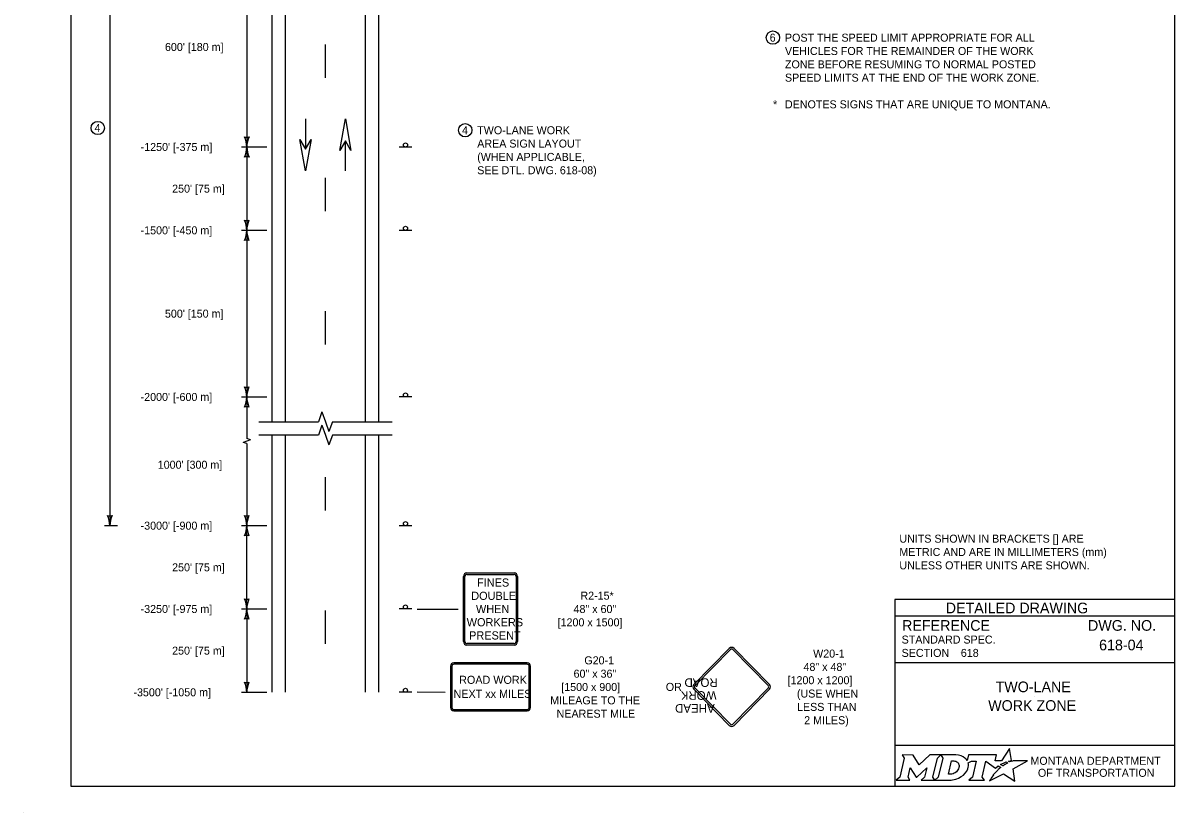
# Model space of a CAD drawing. Extents: x 49991.4 to 50021, y 49987.6 to 50011.4.
# Drawn here: x 49999.98 to 50008.61, y 49999.86 to 50005.79 of the extents above; entities that cross this region are included whole.
import ezdxf

# ---------------------------------------------------------------- set-up
doc = ezdxf.new("R2010")
doc.units = 0
for name, color, linetype in [('Level 1', 7, 'Continuous'), ('Level 2', 7, 'Continuous'), ('Level 3', 7, 'Continuous'), ('Level 6', 7, 'Continuous')]:
    doc.layers.add(name, color=color, linetype=linetype)

msp = doc.modelspace()

# ---------------------------------------------------------------- linework, layer by layer
at = {"layer": 'Level 1'}
for p, q in [((50001.8443, 50002.7972), (50001.8443, 50007.9828)), ((50001.8443, 50002.7972), (50001.8443, 50007.9828)), ((50001.9443, 50002.7972), (50001.9443, 50007.9828)), ((50001.9443, 50002.7972), (50001.9443, 50007.9828)), ((50002.5443, 50002.7972), (50002.5443, 50007.9828)), ((50002.5443, 50002.7972), (50002.5443, 50007.9828)), ((50002.6443, 50002.7972), (50002.6443, 50007.9828)), ((50002.6443, 50002.7972), (50002.6443, 50007.9828)), ((50002.2443, 50005.3756), (50002.2443, 50005.6256)), ((50002.2443, 50005.3756), (50002.2443, 50005.6256)), ((50002.0943, 50005.0679), (50002.0943, 50004.8421)), ((50002.0943, 50005.0679), (50002.0943, 50004.8421)), ((50002.0946, 50005.0679), (50002.0946, 50004.8421)), ((50002.0946, 50005.0679), (50002.0946, 50004.8421)), ((50002.394, 50004.6779), (50002.394, 50004.9037)), ((50002.394, 50004.6779), (50002.394, 50004.9037)), ((50002.8926, 50004.8574), (50002.7966, 50004.8574)), ((50002.8926, 50004.8574), (50002.7966, 50004.8574)), ((50002.2443, 50004.3756), (50002.2443, 50004.6256)), ((50002.2443, 50004.3756), (50002.2443, 50004.6256)), ((50002.8926, 50004.2323), (50002.7966, 50004.2323)), ((50002.8926, 50004.2323), (50002.7966, 50004.2323)), ((50002.2443, 50003.3756), (50002.2443, 50003.6256)), ((50002.2443, 50003.3756), (50002.2443, 50003.6256)), ((50001.9443, 50002.9828), (50001.9443, 50003.4472)), ((50001.9443, 50002.9828), (50001.9443, 50003.4472)), ((50002.5443, 50002.9828), (50002.5443, 50003.4472)), ((50002.5443, 50002.9828), (50002.5443, 50003.4472)), ((50002.8926, 50002.9824), (50002.7966, 50002.9824)), ((50002.8926, 50002.9824), (50002.7966, 50002.9824)), ((50001.8443, 50000.7675), (50001.8443, 50002.6972)), ((50001.8443, 50000.7675), (50001.8443, 50002.6972)), ((50001.9443, 50000.7675), (50001.9443, 50002.6972)), ((50001.9443, 50000.7675), (50001.9443, 50002.6972)), ((50002.5443, 50000.7675), (50002.5443, 50002.6972)), ((50002.5443, 50000.7675), (50002.5443, 50002.6972)), ((50002.6443, 50000.7675), (50002.6443, 50002.6972)), ((50002.6443, 50000.7675), (50002.6443, 50002.6972)), ((50002.2443, 50002.1309), (50002.2443, 50002.3809)), ((50002.2443, 50002.1309), (50002.2443, 50002.3809)), ((50002.8926, 50002.0171), (50002.7966, 50002.0171)), ((50002.8926, 50002.0171), (50002.7966, 50002.0171)), ((50003.2797, 50001.1475), (50003.2797, 50001.637)), ((50003.2902, 50001.1475), (50003.2902, 50001.637)), ((50003.305, 50001.6623), (50003.6594, 50001.6623)), ((50003.305, 50001.6517), (50003.6594, 50001.6517)), ((50003.4822, 50001.6623), (50003.4822, 50001.6623)), ((50003.6742, 50001.637), (50003.6742, 50001.1475)), ((50003.6847, 50001.637), (50003.6847, 50001.1475)), ((50002.2443, 50001.1309), (50002.2443, 50001.3809)), ((50002.2443, 50001.1309), (50002.2443, 50001.3809)), ((50002.8923, 50001.3923), (50002.7963, 50001.3923)), ((50002.8923, 50001.3923), (50002.7963, 50001.3923)), ((50003.6594, 50001.1327), (50003.305, 50001.1327)), ((50003.6594, 50001.1222), (50003.305, 50001.1222)), ((50005.0068, 50000.8261), (50005.272, 50001.0968)), ((50005.0157, 50000.8174), (50005.2808, 50001.0881)), ((50005.2994, 50001.0881), (50005.5646, 50000.8174)), ((50005.3083, 50001.0968), (50005.5735, 50000.8261)), ((50003.7572, 50000.988), (50003.2072, 50000.988)), ((50003.7572, 50000.988), (50003.2072, 50000.988)), ((50003.7572, 50000.978), (50003.2072, 50000.978)), ((50003.7572, 50000.978), (50003.2072, 50000.978)), ((50003.1822, 50000.963), (50003.1822, 50000.653)), ((50003.1822, 50000.963), (50003.1822, 50000.653)), ((50003.1922, 50000.963), (50003.1922, 50000.653)), ((50003.1922, 50000.963), (50003.1922, 50000.653)), ((50003.7722, 50000.653), (50003.7722, 50000.963)), ((50003.7722, 50000.653), (50003.7722, 50000.963)), ((50003.7822, 50000.653), (50003.7822, 50000.963)), ((50003.7822, 50000.653), (50003.7822, 50000.963)), ((50002.8923, 50000.7673), (50002.7963, 50000.7673)), ((50002.8923, 50000.7673), (50002.7963, 50000.7673)), ((50005.272, 50000.5192), (50005.0068, 50000.7899)), ((50005.2808, 50000.5279), (50005.0157, 50000.7986)), ((50005.5646, 50000.7986), (50005.2994, 50000.5279)), ((50005.5735, 50000.7899), (50005.3083, 50000.5192)), ((50003.2072, 50000.638), (50003.7572, 50000.638)), ((50003.2072, 50000.638), (50003.7572, 50000.638)), ((50003.2072, 50000.628), (50003.7572, 50000.628)), ((50003.2072, 50000.628), (50003.7572, 50000.628)), ((49999.9766, 49999.8624), (49999.9766, 49999.8624))]:
    msp.add_line(p, q, dxfattribs=at)
for points in [[(50008.6146, 50011.2628), (50000.3356, 50011.2628), (50000.3356, 50000.0624), (50008.6146, 50000.0624)], [(50002.3523, 50004.8315), (50002.394, 50005.0679), (50002.4359, 50004.8315), (50002.394, 50004.9037)], [(50002.3523, 50004.8315), (50002.394, 50005.0679), (50002.4359, 50004.8315), (50002.394, 50004.9037)], [(50002.1363, 50004.9143), (50002.0946, 50004.6779), (50002.0527, 50004.9143), (50002.0946, 50004.8421)], [(50002.1363, 50004.9143), (50002.0946, 50004.6779), (50002.0527, 50004.9143), (50002.0946, 50004.8421)]]:
    msp.add_lwpolyline(points, close=True, dxfattribs=at)
for centre in [(50002.8446, 50004.8726), (50002.8446, 50004.8726), (50002.8446, 50004.2476), (50002.8446, 50004.2476), (50002.8446, 50002.9976), (50002.8446, 50002.9976), (50002.8446, 50002.0323), (50002.8446, 50002.0323), (50002.8443, 50001.4075), (50002.8443, 50001.4075), (50002.8443, 50000.7825), (50002.8443, 50000.7825)]:
    msp.add_circle(centre, 0.0152, dxfattribs=at)
for centre, radius, start, end in [((50003.305, 50001.637), 0.0253, 90, 180), ((50003.305, 50001.637), 0.0148, 90, 180), ((50003.6594, 50001.637), 0.0253, 0, 90), ((50003.6594, 50001.637), 0.0148, 0, 90), ((50003.305, 50001.1475), 0.0253, 180, 270), ((50003.305, 50001.1475), 0.0148, 180, 270), ((50003.6594, 50001.1475), 0.0148, 270, 360), ((50003.6594, 50001.1475), 0.0253, 270, 360), ((50003.2072, 50000.963), 0.025, 90, 180), ((50003.2072, 50000.963), 0.025, 90, 180), ((50003.2072, 50000.963), 0.015, 90, 180), ((50003.2072, 50000.963), 0.015, 90, 180), ((50003.7572, 50000.963), 0.025, 0, 90), ((50003.7572, 50000.963), 0.025, 0, 90), ((50003.7572, 50000.963), 0.015, 0, 90), ((50003.7572, 50000.963), 0.015, 0, 90), ((50003.2072, 50000.653), 0.025, 180, 270), ((50003.2072, 50000.653), 0.025, 180, 270), ((50003.2072, 50000.653), 0.015, 180, 270), ((50003.2072, 50000.653), 0.015, 180, 270), ((50003.7572, 50000.653), 0.025, 270, 360), ((50003.7572, 50000.653), 0.015, 270, 360), ((50003.7572, 50000.653), 0.025, 270, 360), ((50003.7572, 50000.653), 0.015, 270, 360)]:
    msp.add_arc(centre, radius, start, end, dxfattribs=at)
for centre, major_axis, ratio, start_param, end_param in [((50005.2901, 50001.0786), (0, 0.0258), 0.98963, 5.497787, 7.068583), ((50005.2901, 50001.0786), (0, 0.0134), 0.98, 5.497787, 7.068583), ((50005.0249, 50000.808), (0, 0.0258), 0.98963, 0.785394, 2.356194), ((50005.0249, 50000.808), (0, 0.0134), 0.98, 0.785394, 2.356194), ((50005.5554, 50000.808), (0, 0.0134), 0.98, 3.926991, 5.497787), ((50005.5554, 50000.808), (0, 0.0258), 0.98963, 3.926991, 5.497787), ((50005.2901, 50000.5373), (0, -0.0258), 0.98963, 5.497795, 7.068583), ((50005.2901, 50000.5373), (0, -0.0134), 0.98, 5.497795, 7.068583)]:
    msp.add_ellipse(centre, major_axis=major_axis, ratio=ratio, start_param=start_param, end_param=end_param, dxfattribs=at)
at = {"layer": 'Level 2'}
for p, q in [((50008.6146, 50001.4624), (50006.5146, 50001.4624)), ((50006.5146, 50001.4624), (50006.5146, 50000.0624)), ((50008.6146, 50001.3374), (50006.5146, 50001.3374)), ((50008.2507, 50001.1223), (50008.2507, 50001.1223)), ((50008.6146, 50000.9874), (50006.5146, 50000.9874)), ((50007.0089, 50001.0629), (50007.0089, 50001.0629)), ((50007.5646, 50000.7383), (50007.5646, 50000.7383)), ((50008.6146, 50000.3693), (50006.5146, 50000.3693))]:
    msp.add_line(p, q, dxfattribs=at)
for points in [[(50006.5701, 50000.2974), (50006.5842, 50000.274), (50006.5507, 50000.1307), (50006.525, 50000.1082), (50006.6266, 50000.1082), (50006.6131, 50000.131), (50006.6293, 50000.2011), (50006.673, 50000.1321), (50006.6783, 50000.1321), (50006.7534, 50000.2016), (50006.737, 50000.1305), (50006.7123, 50000.1085), (50006.8139, 50000.1085), (50006.8001, 50000.1318), (50006.8333, 50000.2742)], [(50006.8333, 50000.2742), (50006.8586, 50000.2974), (50006.7762, 50000.2974), (50006.6966, 50000.2244), (50006.6521, 50000.2971), (50006.5701, 50000.2974)], [(50006.9722, 50000.2974), (50006.8586, 50000.2974), (50006.8733, 50000.2745), (50006.8394, 50000.1307), (50006.8139, 50000.1085), (50006.9245, 50000.1085)], [(50007.3771, 50000.2447), (50007.3668, 50000.2503), (50007.3784, 50000.2531), (50007.39, 50000.2551), (50007.3726, 50000.3452), (50007.3131, 50000.2539), (50007.2658, 50000.2532), (50007.2761, 50000.2973), (50007.0669, 50000.2974), (50007.0568, 50000.2549), (50007.051, 50000.2632)], [(50006.9962, 50000.2107), (50006.995, 50000.2026), (50006.9918, 50000.1933), (50006.9876, 50000.1851), (50006.982, 50000.1776), (50006.9755, 50000.1707), (50006.9676, 50000.1644), (50006.9593, 50000.1597), (50006.9502, 50000.1558), (50006.9411, 50000.1535), (50006.9319, 50000.1526), (50006.916, 50000.1526), (50006.9396, 50000.2526), (50006.9556, 50000.2526), (50006.9632, 50000.252), (50006.9708, 50000.2501), (50006.9774, 50000.2471), (50006.9835, 50000.2429), (50006.9883, 50000.2379), (50006.992, 50000.2319), (50006.9947, 50000.2257), (50006.9963, 50000.2183), (50006.9963, 50000.2153), (50006.9962, 50000.2107)], [(50007.0636, 50000.2383), (50007.0882, 50000.2514), (50007.1251, 50000.2514), (50007.0965, 50000.1309), (50007.069, 50000.1082), (50007.1852, 50000.1082), (50007.1682, 50000.1311), (50007.1964, 50000.2513), (50007.2677, 50000.1996), (50007.2888, 50000.2147), (50007.3085, 50000.2038)], [(50007.2527, 50000.1479), (50007.2374, 50000.1235), (50007.2327, 50000.116), (50007.2269, 50000.1074), (50007.2246, 50000.1031), (50007.3299, 50000.1562), (50007.4138, 50000.1011), (50007.4007, 50000.1938), (50007.5076, 50000.2522), (50007.4583, 50000.253), (50007.4282, 50000.2534), (50007.4074, 50000.2537), (50007.4006, 50000.2522), (50007.3957, 50000.251), (50007.3873, 50000.2487), (50007.3771, 50000.2447)], [(50007.3267, 50000.2171), (50007.3243, 50000.2154), (50007.306, 50000.225), (50007.3163, 50000.2307), (50007.3204, 50000.2329), (50007.329, 50000.2369), (50007.3347, 50000.2395), (50007.3426, 50000.2425), (50007.3499, 50000.2452), (50007.3617, 50000.2378), (50007.3577, 50000.2357), (50007.3531, 50000.2332), (50007.3489, 50000.231), (50007.3439, 50000.2281), (50007.342, 50000.227), (50007.3393, 50000.2254), (50007.3368, 50000.224), (50007.3345, 50000.2224), (50007.3319, 50000.2206), (50007.3292, 50000.2188), (50007.3267, 50000.2171)], [(50006.9702, 50000.1158), (50006.9786, 50000.1184), (50006.9916, 50000.1238), (50007.012, 50000.1348)], [(50007.2666, 50000.164), (50007.2666, 50000.164)]]:
    msp.add_lwpolyline(points, dxfattribs=at)
for centre in [(50005.5999, 50005.6777), (50000.537, 50005), (50003.2924, 50004.9831)]:
    msp.add_circle(centre, 0.05, dxfattribs=at)
for centre, radius, start, end in [((50006.9953, 50000.219), 0.0709, 339.53292, 15.85821), ((50006.9513, 50000.2363), 0.1183, 300.91025, 339.13831)]:
    msp.add_arc(centre, radius, start, end, dxfattribs=at)
for centre, major_axis, ratio, start_param, end_param in [((50006.9701, 50000.25), (0.0834, -0.0037), 0.568097, 0.61298, 1.570796), ((50007.0257, 50000.2573), (0.0361, -0.0295), 0.469099, 1.225588, 1.570796), ((50007.2974, 50000.1941), (-0.0112, -0.0097), 0.021651, 3.157348, 6.283185), ((50006.9248, 50000.2568), (0, 0.1484), 0.987302, 3.139398, 3.456847), ((50007.2597, 50000.1559), (-0.00694, -0.00806), 0.008222, 0, 3.137361), ((50007.2764, 50000.1742), (-0.0098, -0.0102), 0.016458, 3.141593, 6.279097)]:
    msp.add_ellipse(centre, major_axis=major_axis, ratio=ratio, start_param=start_param, end_param=end_param, dxfattribs=at)
at = {"layer": 'Level 3'}
for p, q in [((50000.627, 50007.9828), (50000.627, 50002.0173)), ((50001.6543, 50006.3577), (50001.6543, 50004.8576)), ((50001.6143, 50004.8576), (50001.8043, 50004.8576)), ((50001.6543, 50004.8576), (50001.654, 50004.2325)), ((50001.614, 50004.2325), (50001.8043, 50004.2325)), ((50001.654, 50004.2325), (50001.654, 50002.9826)), ((50001.614, 50002.9826), (50001.8043, 50002.9826)), ((50001.654, 50002.9826), (50001.654, 50002.6713)), ((50001.6543, 50002.6519), (50001.6269, 50002.6423)), ((50001.654, 50002.6326), (50001.6269, 50002.6423)), ((50001.6816, 50002.6616), (50001.654, 50002.6713)), ((50001.654, 50002.6326), (50001.654, 50002.0173)), ((50001.6816, 50002.6616), (50001.6543, 50002.6519)), ((50000.587, 50002.0173), (50000.6855, 50002.0173)), ((50001.614, 50002.0173), (50001.8043, 50002.0173)), ((50001.654, 50001.3923), (50001.654, 50002.0173)), ((50001.614, 50001.3923), (50001.8043, 50001.3923)), ((50001.654, 50001.3923), (50001.654, 50000.7675)), ((50002.9323, 50001.3922), (50003.2397, 50001.3922)), ((50001.614, 50000.7675), (50001.8043, 50000.7675)), ((50003.1422, 50000.7672), (50002.9323, 50000.7673))]:
    msp.add_line(p, q, dxfattribs=at)
for centre, radius, start, end in [((50001.6543, 50004.9858), 0.0548, 252.13882, 287.86118), ((50001.4216, 50004.8461), 0.233, 2.82731, 22.07716), ((50001.8764, 50004.8484), 0.2223, 157.45601, 177.63952), ((50001.4322, 50004.8667), 0.2223, 337.45601, 357.63952), ((50001.6543, 50004.7294), 0.0548, 72.13882, 107.86118), ((50001.887, 50004.8691), 0.233, 182.82731, 202.07716), ((50001.654, 50004.3608), 0.0548, 252.13882, 287.86118), ((50001.4213, 50004.2211), 0.233, 2.82731, 22.07716), ((50001.8762, 50004.2234), 0.2223, 157.45601, 177.63952), ((50001.4319, 50004.2417), 0.2223, 337.45601, 357.63952), ((50001.8867, 50004.244), 0.233, 182.82731, 202.07716), ((50001.654, 50004.1043), 0.0548, 72.13882, 107.86118), ((50001.654, 50003.1108), 0.0548, 252.13882, 287.86118), ((50001.4213, 50002.9711), 0.233, 2.82731, 22.07716), ((50001.8762, 50002.9734), 0.2223, 157.45601, 177.63952), ((50001.4319, 50002.9917), 0.2223, 337.45601, 357.63952), ((50001.8867, 50002.9941), 0.233, 182.82731, 202.07716), ((50001.654, 50002.8544), 0.0548, 72.13882, 107.86118), ((50000.627, 50002.1455), 0.0548, 252.13882, 287.86118), ((50000.3943, 50002.0058), 0.233, 2.82731, 22.07716), ((50000.8492, 50002.0081), 0.2223, 157.45601, 177.63952), ((50001.654, 50002.1455), 0.0548, 252.13882, 287.86118), ((50001.4213, 50002.0058), 0.233, 2.82731, 22.07716), ((50001.4319, 50002.0265), 0.2223, 337.45601, 357.63952), ((50001.8762, 50002.0081), 0.2223, 157.45601, 177.63952), ((50001.8867, 50002.0288), 0.233, 182.82731, 202.07716), ((50001.654, 50001.8891), 0.0548, 72.13882, 107.86118), ((50001.654, 50001.5205), 0.0548, 252.13882, 287.86118), ((50001.4213, 50001.3808), 0.233, 2.82731, 22.07716), ((50001.8762, 50001.3831), 0.2223, 157.45601, 177.63952), ((50001.4319, 50001.4015), 0.2223, 337.45601, 357.63952), ((50001.8867, 50001.4038), 0.233, 182.82731, 202.07716), ((50001.654, 50001.2641), 0.0548, 72.13882, 107.86118), ((50001.654, 50000.8957), 0.0548, 252.13882, 287.86118), ((50001.4213, 50000.756), 0.233, 2.82731, 22.07716), ((50001.8762, 50000.7583), 0.2223, 157.45601, 177.63952)]:
    msp.add_arc(centre, radius, start, end, dxfattribs=at)
at = {"layer": 'Level 6'}
for p, q in [((50001.7443, 50002.7972), (50002.1925, 50002.7972)), ((50002.2184, 50002.8703), (50002.1925, 50002.7972)), ((50002.2184, 50002.8703), (50002.2443, 50002.7972)), ((50002.2443, 50002.7972), (50002.2702, 50002.7241)), ((50002.2961, 50002.7972), (50002.2702, 50002.7241)), ((50002.2961, 50002.7972), (50002.7443, 50002.7972)), ((50002.2184, 50002.7703), (50002.1925, 50002.6972)), ((50002.2184, 50002.7703), (50002.2443, 50002.6972)), ((50002.1925, 50002.6972), (50001.7443, 50002.6972)), ((50002.2443, 50002.6972), (50002.2702, 50002.6241)), ((50002.2961, 50002.6972), (50002.2702, 50002.6241)), ((50002.7443, 50002.6972), (50002.2961, 50002.6972))]:
    msp.add_line(p, q, dxfattribs=at)

# ---------------------------------------------------------------- texts
at = {"layer": 'Level 1'}
for s, height, p in [('FINES', 0.06118, (50003.3811, 50001.56)), ('DOUBLE', 0.06118, (50003.3376, 50001.4608)), ('WHEN', 0.06118, (50003.373, 50001.3617)), ('WORKERS', 0.06118, (50003.3036, 50001.2625)), ('PRESENT', 0.06118, (50003.3217, 50001.1634)), ('ROAD WORK', 0.0605, (50003.2469, 50000.831)), ('ROAD WORK', 0.0605, (50003.2469, 50000.831)), ('NEXT xx MILES', 0.0605, (50003.2045, 50000.7255)), ('NEXT xx MILES', 0.0605, (50003.2045, 50000.7255))]:
    msp.add_text(s, height=height, dxfattribs=at).set_placement(p)
for s, p in [('ROAD', (50005.1859, 50000.8725)), ('WORK', (50005.1769, 50000.7757)), ('AHEAD', (50005.1631, 50000.679))]:
    msp.add_text(s, height=0.06453, rotation=180, dxfattribs=at).set_placement(p)
at = {"layer": 'Level 2'}
for s, height, p in [('6', 0.06, (50005.5755, 50005.6477)), ('POST THE SPEED LIMIT APPROPRIATE FOR ALL', 0.06, (50005.69, 50005.6477)), ("600' [180 m]", 0.06, (50001.0409, 50005.5777)), ('VEHICLES FOR THE REMAINDER OF THE WORK', 0.06, (50005.69, 50005.5477)), ('ZONE BEFORE RESUMING TO NORMAL POSTED ', 0.06, (50005.69, 50005.4477)), ('SPEED LIMITS AT THE END OF THE WORK ZONE.', 0.06, (50005.69, 50005.3477)), ('*', 0.06, (50005.6009, 50005.1477)), ('DENOTES SIGNS THAT ARE UNIQUE TO MONTANA.', 0.06, (50005.69, 50005.1477)), ('4', 0.06, (50000.5125, 50004.9703)), ('4', 0.06, (50003.2685, 50004.9532)), ('TWO-LANE WORK', 0.06, (50003.3824, 50004.9531)), ("-1250' [-375 m]", 0.06, (50000.8585, 50004.8276)), ('AREA SIGN LAYOUT', 0.06, (50003.3824, 50004.8531)), ('(WHEN APPLICABLE,', 0.06, (50003.3824, 50004.7531)), ('SEE DTL. DWG. 618-08) ', 0.06, (50003.3824, 50004.6531)), ("250' [75 m]", 0.06, (50001.0947, 50004.5151)), ("-1500' [-450 m]", 0.06, (50000.8582, 50004.2025)), ("500' [150 m]", 0.06, (50001.0406, 50003.5776)), ("-2000' [-600 m]", 0.06, (50000.8582, 50002.9526)), ("1000' [300 m]", 0.06, (50000.9868, 50002.4444)), ("-3000' [-900 m]", 0.06, (50000.8582, 50001.9873)), ('UNITS SHOWN IN BRACKETS [] ARE ', 0.06, (50006.5478, 50001.8898)), ('METRIC AND ARE IN MILLIMETERS (mm) ', 0.06, (50006.5478, 50001.7898)), ("250' [75 m]", 0.06, (50001.0945, 50001.6748)), ('UNLESS OTHER UNITS ARE SHOWN.', 0.06, (50006.5478, 50001.6898)), ('R2-15*', 0.06, (50004.1563, 50001.4622)), ("-3250' [-975 m]", 0.06, (50000.8582, 50001.3623)), ('48" x 60"', 0.06, (50004.1048, 50001.3622)), ('DETAILED DRAWING', 0.0799, (50006.8956, 50001.3599)), ('[1200 x 1500]', 0.06, (50003.9853, 50001.2622)), ('REFERENCE', 0.08, (50006.5682, 50001.229)), ('DWG. NO.', 0.08, (50007.9624, 50001.229)), ('STANDARD SPEC.', 0.06, (50006.5649, 50001.133)), ('618-04', 0.08, (50008.0456, 50001.0823)), ("250' [75 m]", 0.06, (50001.0945, 50001.0499)), ('W20-1', 0.06, (50005.9014, 50001.028)), ('SECTION', 0.06, (50006.5649, 50001.033)), ('618', 0.06, (50007.0089, 50001.0329)), ('618', 0.06, (50007.0089, 50001.0329)), ('G20-1', 0.06, (50004.1856, 50000.9771)), ('48" x 48"', 0.06, (50005.8291, 50000.928)), ('60" x 36"', 0.06, (50004.1049, 50000.8771)), ('[1200 x 1200]', 0.06, (50005.7097, 50000.828)), ('[1500 x 900]', 0.06, (50004.0124, 50000.7771)), ('OR', 0.06, (50004.7966, 50000.778)), ('TWO-LANE', 0.08, (50007.2692, 50000.7683)), ("-3500' [-1050 m]", 0.06, (50000.8043, 50000.7375)), ('MILEAGE TO THE', 0.06, (50003.9297, 50000.6771)), ('(USE WHEN', 0.06, (50005.7798, 50000.728)), ('NEAREST MILE', 0.06, (50003.9778, 50000.5771)), ('LESS THAN', 0.06, (50005.7804, 50000.628)), ('WORK ZONE', 0.08, (50007.214, 50000.6283)), ('2 MILES)', 0.06, (50005.8343, 50000.528)), ('MONTANA DEPARTMENT', 0.06, (50007.5308, 50000.2236)), ('OF TRANSPORTATION', 0.06, (50007.587, 50000.1336))]:
    msp.add_text(s, height=height, dxfattribs=at).set_placement(p)

doc.saveas('drawing.dxf')
